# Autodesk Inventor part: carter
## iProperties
Author: patrick
Shininess: 20.0
Angle Display Precision: 2
Document Length Units: 11269
Document Angle Units: 11283
Document Time Units: 11279
Document Mass Units: 11290
Document Length Units Precision: 3
Document Angle Units Precision: 2
Compacted: True
PropertySet Name: _Private Model Information
Created: 2002-10
Part Number: carter
Material: Par défaut
Document SubType Name: Modélisation
Designer: patrick
Control State: 0
Master: False
Checked Out: False
PropertySet Name: Design Tracking Control
Density: 0.0
Volumn: 0.0
Area: 0.0
PropertySet Name: Model Information
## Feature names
1. Extrusion1
2. Congé1 [Fillet]
3. Coque1
4. Extrusion2
5. Extrusion3
6. Extrusion4
7. Extrusion5
8. Extrusion6
9. Extrusion7
10. Extrusion8
11. Extrusion9
